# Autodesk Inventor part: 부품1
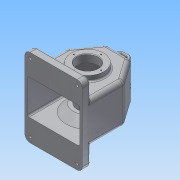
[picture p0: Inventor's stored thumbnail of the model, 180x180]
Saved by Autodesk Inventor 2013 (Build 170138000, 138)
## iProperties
Created: 2016-12
Part Number: 부품1
Material: 알루미늄 6061
Document SubType Name: Modeling
Designer: Administrator
Density: 2.71 g/cm^3
Mass: 1071.7 g
Surface Area: 1151.31 cm^2
Volume: 395.461 cm^3
Author: Administrator
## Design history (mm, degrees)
sketch "스케치1"
  geometry: L1 (-55, 0)-(55, 0); L2 (55, 0)-(55, 80); L3 (55, 80)-(-55, 80); L4 (-55, 80)-(-55, 0); 2 further points
  constraints: 8 end point, 2 parallel, 1 coincident, 1 horizontal, 1 midpoint, 1 perpendicular
  dimensions: "d0" = 110 distance of L3.end L2.end; "d1" = 80 distance of L2.end L1.end
extrude "돌출1" new body sketch "스케치1" stored distance "d2" = 77; taper "d3" = 0 deg
sketch "스케치2"
  geometry: L1 (-55, 80)-(55, 80); L2 (23.491, 125)-(-23.491, 125); L3 (-55, 80)-(55, 80) reference; L4 (-55, 80)-(-23.491, 125); L5 (55, 80)-(23.491, 125); 2 further points
  constraints: 8 end point, 2 midpoint, 1 horizontal, 1 parallel
  dimensions: "d6" = 55 deg angle of L1 L4; "d7" = 55 deg angle of L1 L5; "d8" = 45 vertical distance of L1.end L2.start; "d9" = 90.10672 distance from line of L1.end L4
extrude "돌출2" join sketch "스케치2" stored distance "d10" = 77; taper "d11" = 0 deg
fillet "모깎기1" dims "d12" = 10
fillet "모깎기2" dims "d13" = 8
feature "쉘1" dims "d14" = 5
sketch "스케치3"
  geometry: L1 (-47, -38.5)-(47, -38.5); L2 (55, -30.5)-(55, 30.5); L3 (47, 38.5)-(-47, 38.5); L4 (-55, 30.5)-(-55, -30.5); L5 (-55, -38.5)-(55, 38.5); L6 (55, -38.5)-(-55, 38.5); L7 (-55, 75)-(55, 75); L8 (55, 75)-(55, -75); L9 (55, -75)-(-55, -75); L10 (-55, -75)-(-55, 75); L11 (-55, 75)-(55, -75); L12 (55, 75)-(-55, -75); A1 r 8 centre (47, 30.5) between (55, 30.5) and (47, 38.5); A2 r 8 centre (47, -30.5) between (47, -38.5) and (55, -30.5); A3 r 8 centre (-47, -30.5) between (-55, -30.5) and (-47, -38.5); A4 r 8 centre (-47, 30.5) between (-47, 38.5) and (-55, 30.5); 3 further points
  constraints: 24 end point, 8 point on circle, 8 point on line, 8 tangent, 5 midpoint, 4 centre point, 4 parallel, 3 equal radius, 2 horizontal, 2 perpendicular, 1 coincident
  dimensions: "d15" = 110 distance of L6.end L5.end; "d16" = 77 distance of L5.end L6.start; "d17" = 8 radius of A1; "d18" = 110 distance of L8.end L9.end; "d19" = 150 distance of L7.end L8.end
extrude "돌출3" join sketch "스케치3" distance "d20" = 15; taper "d21" = 0 deg
fillet "모깎기3" dims "d22" = 10
sketch "스케치4"
  geometry: L1 (-47, 15)-(-47, 76.847) reference; L2 (0, 0)-(0, 65); C1 r 37.5 at (0, 65)
  constraints: 2 end point, 1 centre point, 1 coincident, 1 parallel
  dimensions: "d23" = 65 distance of L2.start L2.end; "d24" = 75 diameter of C1
extrude "돌출4" join sketch "스케치4" distance "d25" = 5; taper "d26" = 0 deg
sketch "스케치5"
  geometry: C1 r 37.5 at (0, 0) reference; C2 r 20 at (0, 0); 1 further point
  constraints: 1 centre point, 1 coincident
  dimensions: "d27" = 40 diameter of C2
extrude "돌출5" cut sketch "스케치5" distance "d28" = 100; taper "d29" = 0 deg
sketch "스케치6"
  geometry: C1 r 20 at (0, 65) reference; C2 r 31 at (0, 65); 1 further point
  constraints: 1 centre point, 1 coincident
  dimensions: "d30" = 62 diameter of C2
extrude "돌출6" join sketch "스케치6" distance "d31" = 10; taper "d32" = 0 deg
sketch "스케치7"
  geometry: L1 (0, 0)-(65, 0); L2 (65, 0)-(65, -33.5); L3 (65, -33.5)-(106, -33.5); L4 (92, -19.5)-(65, -19.5); L5 (92, -19.5)-(106, -33.5); L6 (65, -19.5)-(65, -33.5)
  constraints: 12 end point, 2 perpendicular, 1 collinear, 1 horizontal, 1 point on line
  dimensions: "d33" = 65 distance of L1.start L1.end; "d34" = 33.5 distance of L1.end L2.end; "d40" = 135 deg angle of L5 L4; "d41" = 14 distance between parallel lines of L3 L4; "d42" = 41 distance of L2.end L3.end
revolve "회전1" sketch "스케치7" stored, may be unused: angle "d43" = 90 deg
sketch "스케치8"
  geometry: C1 r 20 at (0, 0) reference; C2 r 20 at (0, 0); 1 further point
  constraints: 1 centre point, 1 coincident
  dimensions: "d44" = 40 diameter of C2
extrude "돌출7" cut sketch "스케치8" distance "d45" = 20; taper "d46" = 0 deg
sketch "스케치9"
  geometry: C1 r 20 at (0, 0) reference; 2 further points
  dimensions: "d47" = 29 distance of C1.centre point (0, 29); "d48" = 0 horizontal distance of C1.centre point (0, 29)
hole "구멍1" sketch "스케치9" at (0, 29) diameter "d49" = 2.459; stored, may be unused: countersink angle "d53" = 90 deg, drill point angle "d55" = 118 deg; dims "d50" = 6, "d51" = 4, "d52" = 2, "d54" = 8
sketch "스케치10"
  geometry: C1 r 20 at (0, 0) reference; 2 further points
  dimensions: "d59" = 26 distance of C1.centre point (0, 26); "d60" = 0 horizontal distance of C1.centre point (0, 26)
hole "구멍2" sketch "스케치10" at (0, 26) diameter "d61" = 2.459; stored, may be unused: countersink angle "d65" = 90 deg, drill point angle "d67" = 118 deg; dims "d62" = 6, "d63" = 4, "d64" = 2, "d66" = 8
node "작업 평면1"
sketch "스케치11"
  geometry: L1 (-4.5, 140)-(4.5, 140); L2 (12.5, 132)-(12.5, 125); L3 (-12.5, 125)-(-12.5, 132); L4 (-12.5, 140)-(12.5, 125); L5 (12.5, 140)-(-12.5, 125); L6 (55, 0)-(50, 0) reference; L7 (50, 0)-(50, 76.847) reference; L8 (49.096, 79.715)-(22.381, 117.868) reference; L9 (18.285, 120)-(-18.285, 120) reference; L10 (-22.381, 117.868)-(-49.096, 79.715) reference; L11 (-50, 76.847)-(-50, 0) reference; L12 (-50, 0)-(-55, 0) reference; L13 (-55, 0)-(-55, 76.847) reference; L14 (-53.192, 82.583)-(-26.477, 120.736) reference; L15 (-18.285, 125)-(18.285, 125) reference; L16 (26.477, 120.736)-(53.192, 82.583) reference; L17 (55, 76.847)-(55, 0) reference; L18 (7.5, 125)-(7.5, 132); L19 (4.5, 135)-(-4.5, 135); L20 (-7.5, 132)-(-7.5, 125); L21 (12.5, 125)-(7.5, 125); L22 (-7.5, 125)-(-12.5, 125); A1 r 5 centre (45, 76.847) between (50, 76.847) and (49.096, 79.715) reference; A2 r 5 centre (18.285, 115) between (22.381, 117.868) and (18.285, 120) reference; A3 r 5 centre (-18.285, 115) between (-18.285, 120) and (-22.381, 117.868) reference; A4 r 5 centre (-45, 76.847) between (-49.096, 79.715) and (-50, 76.847) reference; A5 r 10 centre (-45, 76.847) between (-53.192, 82.583) and (-55, 76.847) reference; A6 r 10 centre (-18.285, 115) between (-18.285, 125) and (-26.477, 120.736) reference; A7 r 10 centre (18.285, 115) between (26.477, 120.736) and (18.285, 125) reference; A8 r 10 centre (45, 76.847) between (55, 76.847) and (53.192, 82.583) reference; A9 r 8 centre (-4.5, 132) between (-4.5, 140) and (-12.5, 132); A10 r 8 centre (4.5, 132) between (12.5, 132) and (4.5, 140); A11 r 3 centre (4.5, 132) between (7.5, 132) and (4.5, 135); A12 r 3 centre (-4.5, 132) between (-4.5, 135) and (-7.5, 132); 3 further points
  constraints: 20 end point, 8 point on circle, 4 centre point, 4 parallel, 4 point on line, 4 tangent, 3 midpoint, 2 perpendicular, 1 equal radius, 1 horizontal, 4 other
  dimensions: "d72" = 25 distance of L2.end L3.start; "d73" = 15 distance of L5.start L2.end; "d74" = 8 radius of A9; "d75" = 5 distance between parallel lines of L2 L18; "d76" = 15 distance of L18.start L20.end; "d77" = 42.5 distance between parallel lines of L17 L2; "d78" = 125 distance between parallel lines of L6 L21
extrude "돌출8" join sketch "스케치11" distance "d79" = 8; taper "d80" = 0 deg
sketch "스케치12"
  geometry: A1 r 10 centre (-45, 65) between (-45, 75) and (-55, 65) reference; A2 r 10 centre (45, 65) between (55, 65) and (45, 75) reference; 3 further points
  constraints: 2 coincident
hole "구멍3" sketch "스케치12" at (-45, 65), (45, 65) diameter "d81" = 5; stored, may be unused: countersink angle "d85" = 90 deg, drill point angle "d87" = 118 deg; dims "d82" = 6, "d83" = 12, "d84" = 5, "d86" = 8
sketch "스케치13"
  geometry: A1 r 10 centre (-45, -65) between (-55, -65) and (-45, -75) reference; A2 r 10 centre (45, -65) between (45, -75) and (55, -65) reference; 3 further points
  constraints: 2 coincident
hole "구멍4" sketch "스케치13" at (-45, -65), (45, -65) diameter "d88" = 5; stored, may be unused: countersink angle "d92" = 90 deg, drill point angle "d94" = 118 deg; dims "d89" = 6, "d90" = 12, "d91" = 5, "d93" = 8
chamfer "모따기1" distance "d95" = 1; stored, may be unused: second distance "d96" = 2, angle "d97" = 45 deg
fillet "모깎기4" dims "d98" = 3
fillet "모깎기5" dims "d99" = 3
sketch "스케치14"
  geometry: L1 (-8, 0)-(-8, -58.847) reference; 2 further points
  constraints: 1 other
  dimensions: "d100" = 45 distance of point (30.5, -76.847) point (30.5, -31.847); "d101" = 38.5 distance from line of L1 point (30.5, -31.847)
feature "엠보싱1" sketch "스케치14" dims "d0" = 110, "d1" = 80, "d102" = 0.5, "d103" = 0
fillet "모깎기6" dims "d104" = 1
fillet "모깎기8" dims "d106" = 1
fillet "모깎기9" dims "d107" = 1
fillet "모깎기11" dims "d109" = 1
node "솔리드1"
pattern_circular "원형 패턴1" dims angle "d57" = 360 deg
pattern_circular "원형 패턴2" dims angle "d69" = 360 deg
mirror "대칭3"
node "절단 모서리 투영1"
other parameters: "d71" = -18
